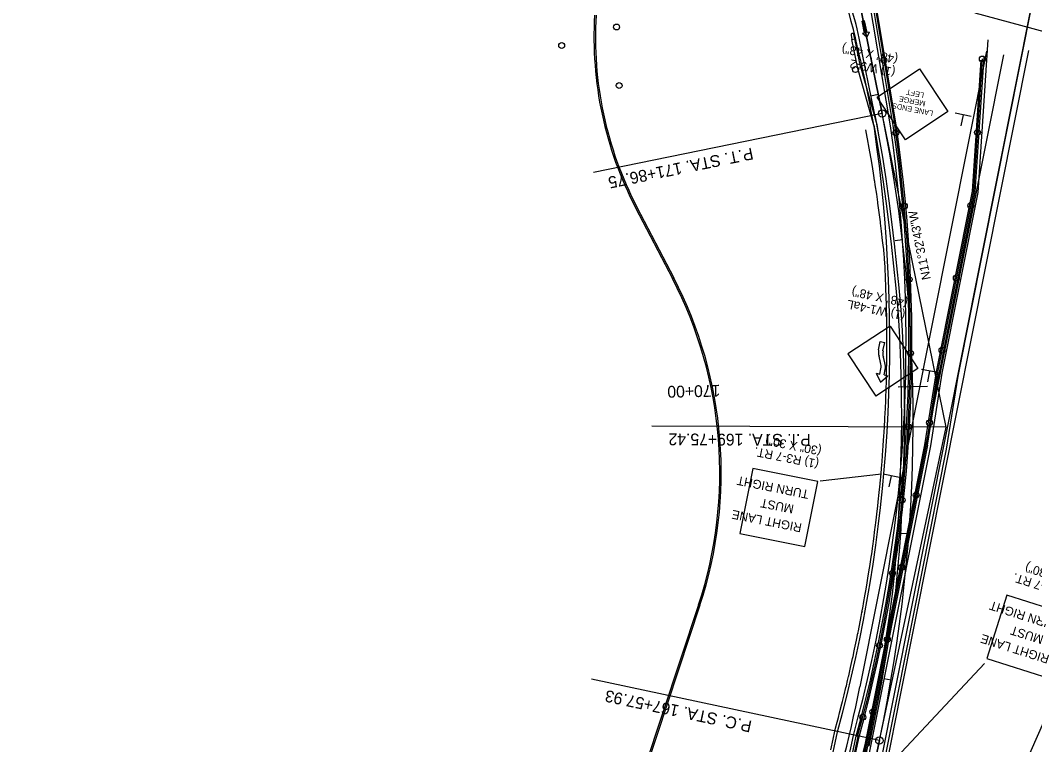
# Model space of a CAD drawing. Extents: x 659657 to 668193, y 633084 to 648639.
# Drawn here: x 661132 to 661821, y 641864 to 642356 of the extents above; entities that cross this region are included whole.
import ezdxf

# ---------------------------------------------------------------- set-up
doc = ezdxf.new("R2010")
doc.units = 0
for name, color, linetype in [('R_Border Prem', 7, 'Continuous'), ('R_MOT_Stage 1', 7, 'Continuous'), ('R_MOT_Stage 1_Striping', 7, 'Continuous'), ('R_MOT_Stage 2', 7, 'Continuous'), ('R_MOT_Stage 2_Striping', 7, 'Continuous'), ('R_MOT_Stage 3', 7, 'Continuous'), ('R_MOT_Stage 3_Striping', 7, 'Continuous'), ('R_MOT_Stage 4_Striping', 7, 'Continuous'), ('R_MOT_Stage 4_Striping_PPM', 7, 'Continuous'), ('R_MOT_Stage 5_Striping_PPM', 7, 'Continuous'), ('R_ROW Annot', 7, 'Continuous'), ('S_EXISTING_ALIGNMENT', 7, 'Continuous'), ('T_Notes', 7, 'Continuous'), ('T_SIGNAL CONTROL CABINET', 7, 'Continuous')]:
    doc.layers.add(name, color=color, linetype=linetype)

msp = doc.modelspace()

# ---------------------------------------------------------------- linework, layer by layer
at = {"layer": 'R_Border Prem'}
msp.add_line((661686.79, 641562.92), (662861.91, 644217.67), dxfattribs=at)
at = {"layer": 'R_MOT_Stage 1'}
for p, q in [((661696.16, 642345.77), (661696.76, 642342.83)), ((661698.72, 642343.23), (661698.12, 642346.17)), ((661696.76, 642342.83), (661698.72, 642343.23)), ((661700.76, 642323.23), (661696.76, 642342.83)), ((661702.72, 642323.63), (661698.72, 642343.23)), ((661702.72, 642323.63), (661700.76, 642323.23)), ((661711.59, 642284.67), (661700.76, 642323.23)), ((661702.72, 642323.63), (661713.55, 642285.05))]:
    msp.add_line(p, q, dxfattribs=at)
for points in [[(661711.58, 642284.67), (661712.92, 642277.5), (661715.45, 642262.72), (661717.7, 642247.89), (661719.74, 642233.03), (661721.55, 642218.75), (661723.34, 642203.86), (661724.93, 642188.95), (661726.5, 642174.04), (661727.91, 642159.11), (661728.76, 642145.08), (661729.49, 642130.08), (661729.98, 642115.08), (661730.26, 642100.09), (661730.43, 642085.09), (661730.28, 642070.46), (661729.83, 642055.47), (661729.17, 642040.48), (661728.49, 642025.5), (661727.91, 642010.52), (661726.89, 641995.55), (661725.58, 641981.14), (661724.12, 641966.21), (661722.14, 641951.34), (661719.87, 641936.51), (661717.38, 641921.7), (661714.74, 641906.91), (661712.04, 641892.87), (661709.14, 641878.15), (661706.2, 641863.44)], [(661713.55, 642285.05), (661714.89, 642277.86), (661717.43, 642263.04), (661719.68, 642248.18), (661721.73, 642233.29), (661723.53, 642219), (661725.32, 642204.09), (661726.92, 642189.16), (661728.49, 642174.24), (661729.9, 642159.26), (661730.76, 642145.19), (661731.49, 642130.16), (661731.98, 642115.14), (661732.26, 642100.12), (661732.43, 642085.09), (661732.28, 642070.42), (661731.82, 642055.39), (661731.17, 642040.39), (661730.49, 642025.42), (661729.9, 642010.41), (661728.89, 641995.39), (661727.57, 641980.95), (661726.11, 641965.98), (661724.12, 641951.06), (661721.84, 641936.19), (661719.35, 641921.36), (661716.71, 641906.55), (661714, 641892.48), (661711.1, 641877.76), (661708.16, 641863.05)]]:
    msp.add_lwpolyline(points, dxfattribs=at)
msp.add_arc((661697.14, 642345.97), 1, 11.44543, 191.44543, dxfattribs=at)
at = {"layer": 'R_MOT_Stage 1_Striping'}
for p, q in [((661717.22, 642292.66), (661678.66, 642481.38)), ((661712.32, 642291.66), (661701.66, 642343.83)), ((661760.74, 642079.57), (661717.22, 642292.66)), ((661715.38, 641866.86), (661760.74, 642079.57)), ((661655.56, 641586.4), (661715.38, 641866.86))]:
    msp.add_line(p, q, dxfattribs=at)
for points in [[(661709.66, 642304.64), (661714.56, 642305.64)], [(661717.22, 642292.66), (661521.26, 642252.63)], [(661712.32, 642291.66), (661714.89, 642277.86), (661717.43, 642263.04), (661719.68, 642248.18), (661721.73, 642233.29), (661723.53, 642219), (661725.32, 642204.09), (661726.92, 642189.16), (661728.49, 642174.24), (661729.9, 642159.26), (661730.76, 642145.19), (661731.49, 642130.16), (661731.98, 642115.14), (661732.26, 642100.12), (661732.43, 642085.09), (661732.28, 642070.42), (661731.82, 642055.39), (661731.17, 642040.39), (661730.49, 642025.42), (661729.9, 642010.41), (661728.89, 641995.39), (661727.57, 641980.95), (661726.11, 641965.98), (661724.12, 641951.06), (661721.84, 641936.19), (661719.35, 641921.36), (661716.71, 641906.55), (661714, 641892.48), (661711.1, 641877.76), (661708.16, 641863.05)], [(661726.06, 642206.45), (661731.02, 642207.04)], [(661728.04, 642107.1), (661748.03, 642107.55)], [(661760.74, 642079.57), (661560.75, 642080.43)], [(661730.47, 642007.76), (661735.46, 642007.4)], [(661715.38, 641866.86), (661519.78, 641908.58)], [(661718.39, 641909.02), (661723.32, 641908.17)]]:
    msp.add_lwpolyline(points, dxfattribs=at)
for centre in [(661717.22, 642292.66), (661715.38, 641866.86)]:
    msp.add_circle(centre, 2.5, dxfattribs=at)
for centre, radius, start, end in [((661531.76, 642309.13), 173.41, 11.54253, 28.301), ((660696.55, 642084.16), 1041.74, 347.96017, 11.54523)]:
    msp.add_arc(centre, radius, start, end, dxfattribs=at)
at = {"layer": 'R_MOT_Stage 2'}
for p, q in [((661724.83, 642284.52), (661708.38, 642383.18)), ((661726.81, 642284.81), (661712.34, 642371.58)), ((661668.51, 641723.82), (661699.65, 641869.84)), ((661670.48, 641723.45), (661701.6, 641869.37))]:
    msp.add_line(p, q, dxfattribs=at)
msp.add_lwpolyline([(661682.36, 641860.69), (661683.9, 641867.9), (661683.9, 641867.91), (661685.06, 641873.31), (661685.62, 641875.37), (661686.71, 641879.45), (661687.51, 641882.47), (661688.33, 641885.59), (661689.91, 641891.75), (661690.31, 641893.34), (661691.21, 641896.96), (661691.21, 641896.97), (661691.21, 641896.97), (661691.44, 641897.91), (661692.64, 641902.84), (661692.94, 641904.09), (661693.78, 641907.63), (661694.41, 641910.28), (661694.53, 641910.8), (661694.54, 641910.84), (661695.82, 641916.46), (661697.2, 641922.66), (661697.51, 641924.04), (661697.76, 641925.19), (661697.78, 641925.28), (661698.32, 641927.81), (661698.54, 641928.86), (661699.85, 641935.09), (661700.79, 641939.72), (661700.79, 641939.72), (661700.77, 641939.61), (661701.11, 641941.29), (661702.33, 641947.53), (661702.53, 641948.57), (661703, 641951.02), (661703.52, 641953.78), (661703.59, 641954.18), (661703.59, 641954.18), (661703.54, 641953.88), (661704.33, 641958.17), (661704.66, 641960), (661705.76, 641966.26), (661706.17, 641968.59), (661706.17, 641968.59), (661706.82, 641972.46), (661707.83, 641978.65), (661707.85, 641978.74), (661708.47, 641982.67), (661708.49, 641982.81), (661708.83, 641985.01), (661709.78, 641991.3), (661710.14, 641993.73), (661710.61, 641997.03), (661710.61, 641997.03), (661710.69, 641997.55), (661710.88, 641998.95), (661711.55, 642003.85), (661712.38, 642010.15), (661712.56, 642011.55), (661713.17, 642016.41), (661713.91, 642022.72), (661714.29, 642026.05), (661714.29, 642026.06), (661714.62, 642029.06), (661715.29, 642035.38), (661715.86, 642041.08), (661715.92, 642041.71), (661716.5, 642048.04), (661716.53, 642048.36), (661717.05, 642054.38), (661717.19, 642056.02), (661717.19, 642056.02), (661717.56, 642060.69), (661718.02, 642067.03), (661718.28, 642070.82), (661718.45, 642073.34), (661718.84, 642079.69), (661719.14, 642085.21), (661719.18, 642085.99), (661719.49, 642092.34), (661719.71, 642097.65), (661719.75, 642098.7), (661719.8, 642099.96), (661719.98, 642105.04), (661720.17, 642111.4), (661720.25, 642114.9), (661720.25, 642114.9), (661720.31, 642117.73), (661720.42, 642124.09), (661720.48, 642129.79), (661720.48, 642130.42), (661720.51, 642136.78), (661720.49, 642143.14), (661720.48, 642144.67), (661720.48, 642144.67), (661720.46, 642147.25), (661720.44, 642149.47), (661720.34, 642155.83), (661720.28, 642158.64), (661720.28, 642158.64), (661720.21, 642162.12), (661720.03, 642168.48), (661719.86, 642173.41), (661719.82, 642174.82), (661719.56, 642181.17), (661719.26, 642187.52), (661719.22, 642188.35), (661719.22, 642188.35), (661718.92, 642193.87), (661718.86, 642194.98), (661718.65, 642196.95), (661718.31, 642200.2), (661717.96, 642203.29), (661717.96, 642203.29), (661717.58, 642206.47), (661716.82, 642212.78), (661716.18, 642218.11), (661716.18, 642218.11), (661716.07, 642219.07), (661715.25, 642225.37), (661714.4, 642231.67), (661714.31, 642232.33), (661714.31, 642232.33), (661713.55, 642237.93), (661712.61, 642244.22), (661712.27, 642246.37), (661712.15, 642247.12), (661712.15, 642247.12), (661711.62, 642250.44), (661710.62, 642256.71), (661709.76, 642261.86), (661709.76, 642261.86), (661709.57, 642262.89), (661708.41, 642269.14), (661707.25, 642275.39), (661707.05, 642276.49), (661707.05, 642276.49), (661706.1, 642281.55)], dxfattribs=at)
for centre in [(661536.84, 642351.3), (661499.55, 642338.73), (661718.46, 642328.8), (661699.13, 642322.41), (661538.6, 642311.57), (661726.56, 642279.48), (661732.31, 642229.82), (661735.62, 642179.93), (661736.48, 642129.94), (661734.88, 642079.97), (661730.83, 642030.14), (661724.34, 641980.57), (661715.42, 641931.38), (661704.1, 641882.68)]:
    msp.add_circle(centre, 2, dxfattribs=at)
for radius, start in [(1017.29, 344.74371), (1019.29, 344.74686)]:
    msp.add_arc((660718.21, 642137.53), radius, start, 8.30799, dxfattribs=at)
at = {"layer": 'R_MOT_Stage 2_Striping'}
for p, q in [((661717.22, 642292.66), (661678.66, 642481.38)), ((661722.85, 642284.23), (661706.36, 642382.86)), ((661760.74, 642079.57), (661717.22, 642292.66)), ((661715.38, 641866.86), (661760.74, 642079.57)), ((661655.73, 641726.21), (661687.02, 641872.91)), ((661666.54, 641724.19), (661697.71, 641870.31)), ((661655.56, 641586.4), (661715.38, 641866.86))]:
    msp.add_line(p, q, dxfattribs=at)
for points in [[(661709.66, 642304.64), (661714.56, 642305.64)], [(661717.22, 642292.66), (661521.26, 642252.63)], [(661726.06, 642206.45), (661731.02, 642207.04)], [(661728.04, 642107.1), (661748.03, 642107.55)], [(661760.74, 642079.57), (661560.75, 642080.43)], [(661730.47, 642007.76), (661735.46, 642007.4)], [(661715.38, 641866.86), (661519.78, 641908.58)], [(661718.39, 641909.02), (661723.32, 641908.17)]]:
    msp.add_lwpolyline(points, dxfattribs=at)
for centre in [(661717.22, 642292.66), (661715.38, 641866.86)]:
    msp.add_circle(centre, 2.5, dxfattribs=at)
for centre, radius, start, end in [((660710.1, 642104.2), 1017.63, 10.09916, 15.23969), ((660696.55, 642084.16), 1041.74, 347.96017, 11.54523), ((660718.21, 642137.53), 1004.29, 344.72294, 8.30799), ((660718.21, 642137.53), 1015.29, 344.74054, 8.30799)]:
    msp.add_arc(centre, radius, start, end, dxfattribs=at)
at = {"layer": 'R_MOT_Stage 3'}
for p, q in [((661816.8, 642335.36), (661729.58, 641897.79)), ((661786.39, 642330.87), (661780.33, 642239.37)), ((661780.33, 642239.37), (661755.9, 642116.78)), ((661748.09, 642067.36), (661755.9, 642116.78)), ((661748.09, 642067.36), (661714.87, 641900.72)), ((661714.87, 641900.72), (661669.72, 641674.19)), ((661729.58, 641897.79), (661674.66, 641622.22))]:
    msp.add_line(p, q, dxfattribs=at)
for centre in [(661785.31, 642329.63), (661782.01, 642279.73), (661777.45, 642230.01), (661767.67, 642180.97), (661757.9, 642131.94), (661749.49, 642082.66), (661740.32, 642033.52), (661730.55, 641984.48), (661720.77, 641935.45), (661711, 641886.41)]:
    msp.add_circle(centre, 2, dxfattribs=at)
at = {"layer": 'R_MOT_Stage 3_Striping'}
for p, q in [((661819.42, 642368.99), (661768.65, 642114.24)), ((661789.17, 642342.61), (661782.29, 642238.98)), ((661782.29, 642238.98), (661757.86, 642116.39)), ((661757.86, 642116.39), (661750.05, 642066.97)), ((661768.65, 642114.24), (661760.84, 642064.82)), ((661750.05, 642066.97), (661716.83, 641900.33)), ((661760.84, 642064.82), (661727.62, 641898.18)), ((661716.83, 641900.33), (661671.68, 641673.8)), ((661727.62, 641898.18), (661682.47, 641671.65))]:
    msp.add_line(p, q, dxfattribs=at)
at = {"layer": 'R_MOT_Stage 4_Striping'}
msp.add_lwpolyline([(661677.79, 641735.12), (661690.5, 641783.57), (661713.89, 641900.92)], dxfattribs=at)
msp.add_arc((660777.38, 642087.58), 954.93, 342.05932, 348.72774, dxfattribs=at)
at = {"layer": 'R_MOT_Stage 4_Striping_PPM'}
for p, q in [((661788.14, 642334.82), (661702.12, 641903.26)), ((661713.89, 641900.92), (661799.91, 642332.48))]:
    msp.add_line(p, q, dxfattribs=at)
msp.add_lwpolyline([(661665.6, 641597.22), (661725.66, 641898.57), (661819.42, 642368.96)], dxfattribs=at)
for radius, start in [(954.93, 348.72774), (942.93, 342.05932)]:
    msp.add_arc((660777.38, 642087.58), radius, start, 348.72774, dxfattribs=at)
at = {"layer": 'R_MOT_Stage 5_Striping_PPM'}
for p, q in [((661788.14, 642334.82), (661702.12, 641903.26)), ((661713.89, 641900.92), (661799.91, 642332.48)), ((661549.73, 642228.62), (661574.77, 642180.49)), ((661550.62, 642229.09), (661575.65, 642180.95)), ((661592.51, 641959.01), (661549.73, 641829.82)), ((661593.45, 641958.69), (661550.69, 641829.55))]:
    msp.add_line(p, q, dxfattribs=at)
msp.add_lwpolyline([(661665.6, 641597.22), (661725.66, 641898.57), (661819.42, 642368.96)], dxfattribs=at)
for centre, radius, start, end in [((660777.38, 642087.58), 954.93, 348.72774, 348.72774), ((661771.97, 642344.21), 250.5, 176.54523, 207.47982), ((661771.97, 642344.21), 249.5, 176.54523, 207.47982), ((661321.48, 642048.75), 285.5, 341.67909, 27.47982), ((661321.48, 642048.75), 286.5, 341.67909, 27.47982), ((660777.38, 642087.58), 942.93, 342.05932, 348.72774), ((660777.38, 642087.58), 954.93, 336.60619, 348.72774)]:
    msp.add_arc(centre, radius, start, end, dxfattribs=at)
at = {"layer": 'R_ROW Annot'}
for p, q in [((661713.81, 642303.61), (661742.65, 642322.87)), ((661742.65, 642322.87), (661761.91, 642294.03)), ((661733.07, 642274.77), (661713.81, 642303.61)), ((661761.91, 642294.03), (661733.07, 642274.77)), ((661766.81, 642293.05), (661777.85, 642290.85)), ((661772.27, 642291.79), (661770.77, 642284.26)), ((661716.92, 642047.75), (661675.18, 642042.93)), ((661717.95, 642047.87), (661728.98, 642045.67)), ((661723.4, 642046.62), (661721.9, 642039.09)), ((661677.17, 641802.33), (661786.91, 641919.17))]:
    msp.add_line(p, q, dxfattribs=at)
for points in [[(661620.62, 642007.37), (661664.75, 641998.58), (661673.55, 642042.71), (661629.42, 642051.5)], [(661788.37, 641922.69), (661831.27, 641909.1), (661844.86, 641952), (661801.96, 641965.59)]]:
    msp.add_lwpolyline(points, close=True, dxfattribs=at)
at = {"layer": 'S_EXISTING_ALIGNMENT'}
for p, q in [((661678.66, 642481.38), (661717.22, 642292.66)), ((661715.38, 641866.86), (661655.56, 641586.4))]:
    msp.add_line(p, q, dxfattribs=at)
msp.add_arc((660696.55, 642084.16), 1041.74, 347.96017, 11.54523, dxfattribs=at)
at = {"layer": 'T_Notes'}
for p, q in [((661899.09, 642328.71), (661780.53, 642360.66)), ((661722.73, 642148.26), (661694.01, 642129.39)), ((661722.73, 642148.26), (661741.6, 642119.52)), ((661714.86, 642132.16), (661716.02, 642137.73)), ((661716.02, 642137.73), (661718.98, 642137.12)), ((661717.82, 642131.55), (661718.98, 642137.12)), ((661694.01, 642129.39), (661712.86, 642100.65)), ((661716.17, 642123.61), (661715.19, 642127.8)), ((661719.08, 642123.23), (661718.15, 642127.18)), ((661741.6, 642119.52), (661712.86, 642100.65)), ((661715.63, 642115.72), (661716.36, 642119.23)), ((661718.59, 642115.11), (661719.37, 642118.87)), ((661744.06, 642119.06), (661755.12, 642117.02)), ((661749.53, 642117.89), (661748.14, 642110.33)), ((661713.16, 642116.23), (661716.05, 642110.29)), ((661713.16, 642116.23), (661715.63, 642115.72)), ((661716.05, 642110.29), (661721.06, 642114.6)), ((661718.59, 642115.11), (661721.06, 642114.6))]:
    msp.add_line(p, q, dxfattribs=at)
for centre, start, end in [((661722.19, 642130.47), 166.95516, 200.71306), ((661725.18, 642129.84), 166.95516, 200.71306), ((661709.03, 642120.93), 346.95516, 20.71306), ((661712.04, 642120.57), 346.95516, 20.71306)]:
    msp.add_arc(centre, 7.52, start, end, dxfattribs=at)
at = {"layer": 'T_SIGNAL CONTROL CABINET'}
for p, q in [((661710.24, 642378.12), (661725.82, 642284.66)), ((661705.25, 642355.62), (661703.6, 642355.27)), ((661705.32, 642347.18), (661703.6, 642355.27)), ((661706.97, 642347.53), (661705.25, 642355.62)), ((661705.32, 642347.18), (661703.95, 642346.88)), ((661706.75, 642344.49), (661703.95, 642346.88)), ((661708.35, 642347.82), (661706.75, 642344.49)), ((661708.35, 642347.82), (661706.97, 642347.53)), ((661784.25, 642328.73), (661778.37, 642239.76)), ((661785.31, 642329.63), (661779.36, 642239.63)), ((661778.37, 642239.76), (661753.94, 642117.17)), ((661779.36, 642239.63), (661754.92, 642116.98)), ((661753.94, 642117.17), (661746.12, 642067.75)), ((661754.92, 642116.98), (661747.11, 642067.55)), ((661746.12, 642067.75), (661712.91, 641901.11)), ((661747.11, 642067.55), (661713.89, 641900.92)), ((661712.91, 641901.11), (661667.76, 641674.58)), ((661713.89, 641900.92), (661668.74, 641674.38)), ((661700.63, 641869.61), (661669.49, 641723.64))]:
    msp.add_line(p, q, dxfattribs=at)
msp.add_arc((660718.21, 642137.53), 1018.29, 344.74529, 8.30799, dxfattribs=at)

# ---------------------------------------------------------------- texts
at = {"layer": 'R_MOT_Stage 1_Striping'}
for s, height, rotation, p in [('P.T. STA. 171+86.75', 8, 191.54523, (661628.75, 642269.48)), ('N11%%d32\'43"W', 6, 101.54523, (661750.34, 642180.29)), ('170+00', 8, 181.27409, (661607.22, 642108.42)), ('P.I. STA. 169+75.42', 8, 179.7527, (661668.78, 642074.96)), ('P.C. STA. 167+57.93', 8, 167.96017, (661629.22, 641880.13))]:
    msp.add_text(s, height=height, rotation=rotation, dxfattribs=at).set_placement(p)
at = {"layer": 'R_MOT_Stage 2_Striping'}
for s, height, rotation, p in [('P.T. STA. 171+86.75', 8, 191.54523, (661628.75, 642269.48)), ('N11%%d32\'43"W', 6, 101.54523, (661750.34, 642180.29)), ('170+00', 8, 181.27409, (661607.22, 642108.42)), ('P.I. STA. 169+75.42', 8, 179.7527, (661668.78, 642074.96)), ('P.C. STA. 167+57.93', 8, 167.96017, (661629.22, 641880.13))]:
    msp.add_text(s, height=height, rotation=rotation, dxfattribs=at).set_placement(p)
at = {"layer": 'R_ROW Annot'}
for s, height, rotation, p in [('(48" X 48")', 6, 168.72774, (661728.39, 642332.11)), ('(1) W9-2', 6, 168.72774, (661726.63, 642323.29)), ('MERGE', 3.612, 168.72774, (661746.95, 642300.92)), ('LEFT', 3.612, 168.72774, (661746.01, 642306.63)), ('LANE ENDS', 3.613, 168.72774, (661752.17, 642294.35)), ('(30" X 30")', 6, 168.72774, (661676.44, 642066.18)), ('(1) R3-7 RT.', 6, 168.72774, (661674.68, 642057.36)), ('TURN RIGHT', 6.01, 168.72774, (661667.89, 642036.8)), ('MUST', 6.01, 168.72774, (661657.67, 642026.78)), ('RIGHT LANE', 6.01, 168.72774, (661663.06, 642014.08)), ('(30" X 30")', 6, 162.42257, (661852.41, 641975.84)), ('(1) R3-7 RT.', 6, 162.42257, (661849.69, 641967.26)), ('TURN RIGHT', 6.01, 162.42257, (661838.58, 641946.76)), ('MUST', 6.01, 162.42257, (661827.33, 641937.92)), ('RIGHT LANE', 6.01, 162.42257, (661831.29, 641924.7))]:
    msp.add_text(s, height=height, rotation=rotation, dxfattribs=at).set_placement(p)
at = {"layer": 'T_Notes'}
for s, p in [('(48" X 48")', (661735.11, 642166.82)), ('(1) W1-4aL', (661733.28, 642158.01))]:
    msp.add_text(s, height=6, rotation=168.28017, dxfattribs=at).set_placement(p)

doc.saveas('drawing.dxf')
